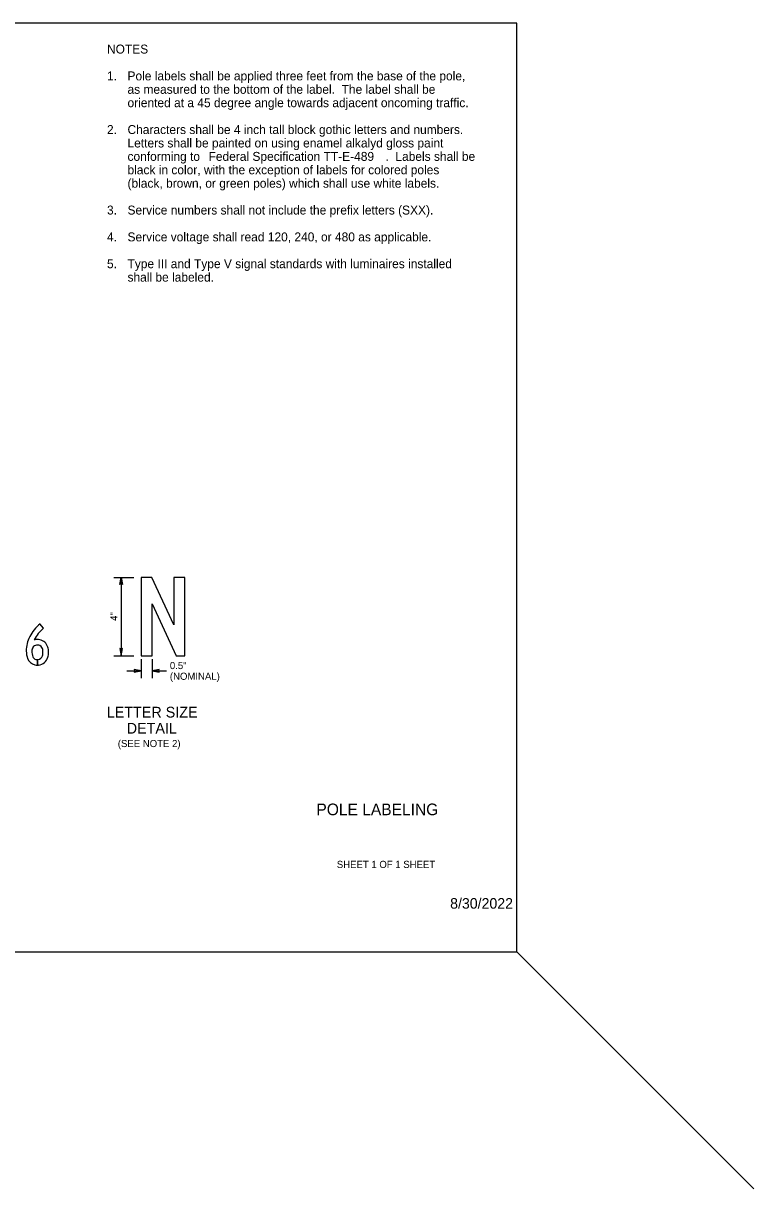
# Model space of a CAD drawing. Extents: x 99862 to 103680, y 99470 to 102076.
# Drawn here: x 102047 to 103680, y 99470 to 102076 of the extents above; entities that cross this region are included whole.
import ezdxf

# ---------------------------------------------------------------- set-up
doc = ezdxf.new("R2010")
doc.units = 0
for name, color, linetype in [('Level 1', 7, 'Continuous'), ('Level 10', 7, 'Continuous'), ('Level 15', 7, 'Continuous'), ('Level 20', 7, 'Continuous'), ('Level 60', 7, 'Continuous'), ('Level 62', 7, 'Continuous')]:
    doc.layers.add(name, color=color, linetype=linetype)

msp = doc.modelspace()

# ---------------------------------------------------------------- linework, layer by layer
at = {"layer": 'Level 1'}
msp.add_line((103150, 100000), (103680.3, 99469.7), dxfattribs=at)
msp.add_lwpolyline([(99862, 99999.5), (103151, 99999.5), (103151, 102075.5), (99862, 102075.5)], close=True, dxfattribs=at)
at = {"layer": 'Level 10'}
msp.add_lwpolyline([(102389.2, 100661.5), (102408.4, 100661.5), (102408.4, 100836.2), (102384, 100836.2), (102384, 100730.6), (102334.7, 100836.2), (102310.6, 100836.2), (102310.6, 100661.5), (102335, 100661.5), (102335, 100777.7)], close=True, dxfattribs=at)
for points in [[(102092.3, 100722.7), (102084.5, 100732.4)], [(102078.6, 100652.9), (102078.6, 100640.4)], [(102078.6, 100640.4), (102078.6, 100652.9)]]:
    msp.add_lwpolyline(points, dxfattribs=at)
for centre, major_axis, start_param, end_param in [((102137.7, 100665.7), (0, 85.3), 0.672912, 1.103825), ((102137.7, 100665.7), (0, 72.9), 0.672912, 1.129373), ((102125.5, 100671.8), (0, 71.7), 1.103825, 1.570796), ((102077.9, 100674.3), (0, 23.3), 0.141499, 0.265027), ((102078.6, 100669.9), (0, 27.7), 6.283185, 6.424685), ((102078.6, 100669.9), (0, 27.7), 6.08431, 6.283185), ((102079.4, 100674.1), (0, 23.5), 5.002719, 6.08431), ((102103.8, 100671.8), (0, 49.9), 1.570796, 1.91455), ((102081.6, 100671.8), (0, 15.3), 0.97817, 1.570796), ((102103.8, 100671.8), (0, 37.5), 1.570796, 1.91455), ((102077.9, 100674.3), (0, 10.9), 0.141499, 0.97817), ((102078.6, 100669.9), (0, 15.3), 6.283185, 6.424685), ((102078.6, 100669.9), (0, 15.3), 6.08431, 6.283185), ((102079.4, 100674.1), (0, 11.1), 5.002719, 6.08431), ((102062.6, 100669.1), (0, 28.6), 4.712389, 5.002719), ((102062.6, 100669.1), (0, 28.6), 4.43884, 4.712389), ((102062.6, 100669.1), (0, 41), 4.712389, 5.002719), ((102062.6, 100669.1), (0, 41), 4.43884, 4.712389), ((102077.3, 100662.4), (0, 21.8), 1.91455, 2.930089), ((102077.3, 100662.4), (0, 9.36), 1.91455, 2.930089), ((102078.6, 100668.2), (0, 27.7), 2.930089, 3.141593), ((102078.6, 100668.2), (0, 15.3), 2.930089, 3.141593), ((102078.6, 100668.2), (0, 15.3), 3.141738, 3.24973), ((102078.6, 100668.2), (0, 27.7), 3.141673, 3.24973), ((102079, 100664.5), (0, 11.6), 3.24973, 4.43884), ((102079, 100664.5), (0, 24), 3.24973, 4.43884)]:
    msp.add_ellipse(centre, major_axis=major_axis, ratio=0.999992, start_param=start_param, end_param=end_param, dxfattribs=at)
at = {"layer": 'Level 15'}
for p, q in [((102249.8, 100836.2), (102294.6, 100836.2)), ((102265.8, 100836.2), (102265.8, 100661.5)), ((102249.8, 100661.5), (102294.6, 100661.5)), ((102310.6, 100653.5), (102310.6, 100611.5)), ((102335, 100653.5), (102335, 100611.5)), ((102278.6, 100627.5), (102310.6, 100627.5)), ((102335, 100627.5), (102367, 100627.5))]:
    msp.add_line(p, q, dxfattribs=at)
for points in [[(102265.8, 100836.2), (102268.9, 100820.5), (102265.8, 100821.2), (102262.7, 100820.5)], [(102265.8, 100661.5), (102268.9, 100677.2), (102265.8, 100676.5), (102262.7, 100677.2)], [(102310.6, 100627.5), (102294.8, 100630.5), (102295.6, 100627.5), (102294.8, 100624.4)], [(102335, 100627.5), (102350.8, 100624.4), (102350, 100627.5), (102350.8, 100630.5)]]:
    msp.add_lwpolyline(points, close=True, dxfattribs=at)
at = {"layer": 'Level 60'}
msp.add_line((103151, 102075.5), (103151, 102075.5), dxfattribs=at)

# ---------------------------------------------------------------- texts
at = {"layer": 'Level 15'}
msp.add_text('8/30/2022', height=23.62, dxfattribs=at).set_placement((103001.6, 100095.8))
at = {"layer": 'Level 20'}
for s, height, p in [('NOTES', 20, (102234.3, 102007.9)), ('1.', 20, (102234.3, 101947.9)), ('Pole labels shall be applied three feet from the base of the pole,', 20, (102280.2, 101947.9)), ('as measured to the bottom of the label.  The label shall be', 20, (102280.2, 101917.9)), ('oriented at a 45 degree angle towards adjacent oncoming traffic.', 20, (102280.2, 101887.9)), ('2.', 20, (102234.3, 101827.9)), ('Characters shall be 4 inch tall block gothic letters and numbers.', 20, (102280.2, 101827.9)), ('Letters shall be painted on using enamel alkalyd gloss paint', 20, (102280.2, 101797.9)), ('conforming to ', 20, (102280.2, 101767.9)), ('Federal Specification TT-E-489', 20, (102461.4, 101767.9)), ('.  Labels shall be', 20, (102856.9, 101767.9)), ('black in color, with the exception of labels for colored poles', 20, (102280.2, 101737.9)), ('(black, brown, or green poles) which shall use white labels.', 20, (102280.2, 101707.9)), ('3.', 20, (102234.3, 101647.9)), ('Service numbers shall not include the prefix letters (SXX).', 20, (102280.2, 101647.9)), ('4.', 20, (102234.3, 101587.9)), ('Service voltage shall read 120, 240, or 480 as applicable.', 20, (102280.2, 101587.9)), ('5.', 20, (102234.3, 101527.9)), ('Type III and Type V signal standards with luminaires installed', 20, (102280.2, 101527.9)), ('shall be labeled.', 20, (102280.2, 101497.9)), ('0.5"', 16, (102374.9, 100631.5)), ('(NOMINAL)', 16, (102374.9, 100607.5)), ('LETTER SIZE', 24, (102233.6, 100523.2)), ('DETAIL', 24, (102278.4, 100487.2)), ('(SEE NOTE 2)', 16, (102258.5, 100457.1))]:
    msp.add_text(s, height=height, dxfattribs=at).set_placement(p)
msp.add_text('4"', height=16, rotation=90, dxfattribs=at).set_placement((102257.8, 100739.3))
at = {"layer": 'Level 62'}
for s, height, p in [('POLE LABELING', 26, (102702.6, 100304.8)), ('SHEET 1 OF 1 SHEET', 16, (102748.2, 100186.8))]:
    msp.add_text(s, height=height, dxfattribs=at).set_placement(p)

doc.saveas('drawing.dxf')
